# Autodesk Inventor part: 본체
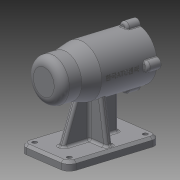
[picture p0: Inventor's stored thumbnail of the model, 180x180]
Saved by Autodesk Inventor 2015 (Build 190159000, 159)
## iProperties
Created: 2019-07
Part Number: 본체
Material: 일반
Document SubType Name: Modeling
Designer: now
Density: 1 g/cm^3
Appearance: 기본값
Author: now
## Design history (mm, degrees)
sketch "스케치1"
  geometry: C1 r 30 at (0, 0); 1 further point
  constraints: 1 centre point, 1 coincident
  dimensions: "d0" = 60 diameter of C1
extrude "돌출1" new body sketch "스케치1" distance "d1" = 67; taper "d2" = 0 deg
node "작업 평면1"
sketch "스케치3"
  geometry: C1 r 25 at (0, 0); 1 further point
  constraints: 1 centre point, 1 coincident
  dimensions: "d4" = 50 diameter of C1
extrude "돌출2" join sketch "스케치3" distance "d5" = 25; taper "d6" = 0 deg
sketch "스케치6"
  geometry: L1 (30, 67)-(30, 0) reference; L2 (30, 0)-(-30, 0) reference; L3 (-30, 0)-(-30, 67) reference; L4 (-30, 67)-(30, 67) reference; L5 (-25, 87)-(-25, 112) reference; L6 (-25, 112)-(25, 112) reference; L7 (25, 112)-(25, 87) reference; L8 (25, 87)-(-25, 87) reference; L9 (25, 87)-(30, 67); L10 (0, 112)-(0, 0)
  constraints: 4 end point, 1 midpoint, 1 vertical
revolve "회전1" sketch "스케치6" stored, may be unused: angle "d7" = 90 deg
node "작업 평면2"
sketch "스케치7"
  geometry: L1 (35, 112)-(-35, 112); L2 (-35, 112)-(-35, 0); L3 (-35, 0)-(35, 0); L4 (35, 0)-(35, 112); 2 further points
  constraints: 8 end point, 2 coincident, 2 parallel, 1 horizontal, 1 midpoint, 1 perpendicular
  dimensions: "d9" = 70 distance of L2.end L3.end; "d10" = 112 distance of L3.end L1.start
extrude "돌출3" join sketch "스케치7" distance "d11" = 10; taper "d12" = 0 deg
fillet "모깎기1" dims "d13" = 10
sketch "스케치8"
  geometry: A1 r 10 centre (-25, -10) between (-25, 0) and (-35, -10) reference; A2 r 10 centre (-25, -102) between (-35, -102) and (-25, -112) reference; A3 r 10 centre (25, -102) between (25, -112) and (35, -102) reference; A4 r 10 centre (25, -10) between (35, -10) and (25, 0) reference; 1 further point
hole "구멍1" sketch "스케치8" at (-25, -102), (25, -102), (25, -10), (-25, -10) diameter "d14" = 6; stored, may be unused: countersink angle "d18" = 90 deg, drill point angle "d20" = 118 deg; dims "d15" = 6, "d16" = 4, "d17" = 2, "d19" = 8
sketch "스케치9"
  geometry: L1 (-35, -10)-(-35, -102) reference; L2 (-25, -112)-(25, -112) reference; L3 (35, -102)-(35, -10) reference; L4 (25, 0)-(-25, 0) reference; L5 (-28, -60)-(28, -60); L6 (28, -60)-(28, -52); L7 (28, -52)-(-28, -52); L8 (-28, -52)-(-28, -60); L9 (-4, -92)-(4, -92); L10 (4, -92)-(4, -25); L11 (4, -25)-(-4, -25); L12 (-4, -25)-(-4, -92); 7 further points
  constraints: 16 end point, 6 midpoint, 4 parallel, 2 horizontal, 2 perpendicular, 1 horizontal alignment, 1 vertical alignment
  dimensions: "d21" = 8 distance of L7.end L5.start; "d22" = 7 distance between parallel lines of L1 L8; "d23" = 8 distance of L10.end L11.end; "d24" = 25 distance between parallel lines of L4 L11; "d25" = 20 distance between parallel lines of L2 L9; "d26" = 31 distance between parallel lines of L1 L12
extrude "돌출4" join sketch "스케치9" stored distance "d27" = 10; taper "d28" = 0 deg
feature "면 기울기1" dims angle "d29" = 20 deg
feature "면 기울기2" dims angle "d30" = 10 deg
sketch "스케치10"
  geometry: C1 r 6 at (0, 30); C2 r 6 at (-30, 0); C3 r 6 at (0, -30); C4 r 6 at (30, 0); 1 further point
  constraints: 4 centre point, 2 vertical alignment, 10 other
  dimensions: "d31" = 12 diameter of C1; "d34" = 360 deg dimension on point (0, 0) C1.centre (derived)
extrude "돌출5" join sketch "스케치10" distance "d36" = 16; taper "d37" = 0 deg
fillet "모깎기2" dims "d38" = 10
fillet "모깎기3" dims "d39" = 3
fillet "모깎기4" dims "d40" = 1
fillet "모깎기5" dims "d41" = 3
fillet "모깎기6" dims "d42" = 3
sketch "스케치11"
  geometry: A1 r 30 centre (0, 0) between (29.226, 6.771) and (6.771, 29.226) reference; 1 further point
  constraints: 1 vertical alignment
  dimensions: "d43" = 30 distance of A1.centre point (0, 30)
hole "구멍2" sketch "스케치11" at (0, 30) diameter "d44" = 3.242; stored, may be unused: countersink angle "d48" = 90 deg, drill point angle "d50" = 118 deg; dims "d45" = 8, "d46" = 4, "d47" = 2, "d49" = 11
sketch "스케치12"
  geometry: L1 (25, 102)-(25, 87) reference; L2 (25, 87)-(30, 67) reference; L3 (30, 67)-(30, 17) reference; L4 (31, 16)-(33, 16) reference; L5 (36, 13)-(36, 0) reference; L6 (36, 0)-(31.621, 0) reference; L7 (31.621, 0)-(31.621, 11) reference; L8 (31.621, 11)-(30, 11.974) reference; L9 (30, 11.974)-(28.379, 11) reference; L10 (28.379, 11)-(28.379, 0) reference; L11 (28.379, 0)-(-28.379, 0) reference; L12 (-28.379, 0)-(-28.379, 11) reference; L13 (-28.379, 11)-(-30, 11.974) reference; L14 (-30, 11.974)-(-31.621, 11) reference; L15 (-31.621, 11)-(-31.621, 0) reference; L16 (-31.621, 0)-(-36, 0) reference; L17 (-36, 0)-(-36, 13) reference; L18 (-33, 16)-(-31, 16) reference; L19 (-30, 17)-(-30, 25) reference; L20 (-30, 25)-(-67, 25) reference; L21 (-70, 22)-(-70, 0) reference; L22 (-70, 0)-(-80, 0) reference; L23 (-80, 0)-(-80, 112) reference; L24 (-80, 112)-(-70, 112) reference; L25 (-70, 112)-(-70, 94.101) reference; L26 (-68.026, 91.282)-(-27.607, 76.57) reference; L27 (-27.607, 76.57)-(-25, 87) reference; L28 (-25, 87)-(-25, 102) reference; L29 (-15, 112)-(15, 112) reference; L30 (0, 112)-(0, 0); L31 (21, 0)-(21, 15); L32 (21, 15)-(24, 15); L33 (24, 15)-(24, 69); L34 (24, 69)-(21, 69); L35 (21, 69)-(21, 81); L36 (21, 81)-(17.5, 81); L37 (17.5, 81)-(17.5, 99); L38 (17.5, 99)-(16, 99); L39 (16, 99)-(16, 103); L40 (16, 103)-(10.5, 103); L41 (10.5, 103)-(10.5, 106); L42 (10.5, 106)-(0, 106); L43 (0, 106)-(0, 0); L44 (21, 0)-(0, 0); L45 (1.621, 0)-(-1.621, 0) reference; A1 r 10 centre (15, 102) between (25, 102) and (15, 112) reference; A2 r 1 centre (31, 17) between (30, 17) and (31, 16) reference; A3 r 3 centre (33, 13) between (36, 13) and (33, 16) reference; A4 r 3 centre (-33, 13) between (-33, 16) and (-36, 13) reference; A5 r 1 centre (-31, 17) between (-31, 16) and (-30, 17) reference; A6 r 3 centre (-67, 22) between (-67, 25) and (-70, 22) reference; A7 r 3 centre (-67, 94.101) between (-70, 94.101) and (-68.026, 91.282) reference; A8 r 10 centre (-15, 102) between (-15, 112) and (-25, 102) reference
  constraints: 30 end point, 11 perpendicular, 2 collinear, 2 point on line, 2 vertical, 1 midpoint
  dimensions: "d54" = 15 distance of L31.start L31.end; "d55" = 3 distance of L40.end L41.end; "d56" = 4 distance of L38.end L39.end; "d57" = 18 distance of L36.end L37.end; "d58" = 12 distance of L34.end L35.end; "d59" = 54 distance of L32.end L33.end; "d60" = 21 diameter of L41 L30; "d61" = 32 diameter of L39 L30; "d62" = 35 diameter of L37 L30; "d63" = 42 diameter of L35 L30; "d64" = 48 diameter of L33 L30; "d65" = 42 diameter of L31 L30
revolve "회전2" sketch "스케치12" stored, may be unused: angle "d66" = 90 deg
fillet "모깎기7" dims "d67" = 0.3
fillet "모깎기8" dims "d68" = 3
chamfer "모따기1" distance "d69" = 3; stored, may be unused: second distance "d70" = 2, angle "d71" = 45 deg
chamfer "모따기2" distance "d72" = 1; stored, may be unused: second distance "d73" = 2, angle "d74" = 45 deg
node "작업 평면3"
sketch "스케치13"
  geometry: L1 (6.771, 0)-(29.226, 0) reference; L2 (5.998, 0)-(-5.998, 0) reference; 3 further points
  constraints: 1 midpoint, 1 vertical alignment, 1 other
  dimensions: "d76" = 42 distance from line of point (0, 42) L1
feature "엠보싱1" sketch "스케치13" dims "d1" = 67, "d9" = 70, "d10" = 112, "d77" = 0.5, "d78" = 0
node "솔리드1"
pattern_circular "원형 패턴1" dims angle "d52" = 360 deg
node "절단 모서리 투영2"
node "절단 모서리 투영3"
other parameters: "d3" = 112
